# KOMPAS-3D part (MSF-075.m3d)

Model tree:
1. Ось X
2. Ось Y
3. Ось Z
4. Начало координат  (labels: Операция без истории:1)

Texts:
  Линия-выноска #1
  Линия-выноска #2
  Линия-выноска #3
  Отклонения формы и база
  Марка координационной оси
  Марка/позиционное обозначение с линией-выноской
  Марка/позиционное обозначение на линии
  Марка/позиционное обозначение без линии-выноски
